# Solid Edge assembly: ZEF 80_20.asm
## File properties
Title: Zylinder
Author: ahadarics
Template: iso metric assembly.asm
Last saved by: ahadarics
Revision: 6
Application: Solid Edge
Username: ahadarics
Dokumentum tartalom típus: 1
Document Number: ZEF 80/20
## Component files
Profilrohr.par
Kolbenstange.par
Kit_1.par
Kit_2.par
Mutter.par
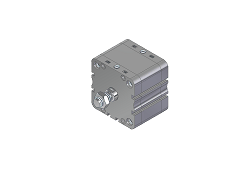
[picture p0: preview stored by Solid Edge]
